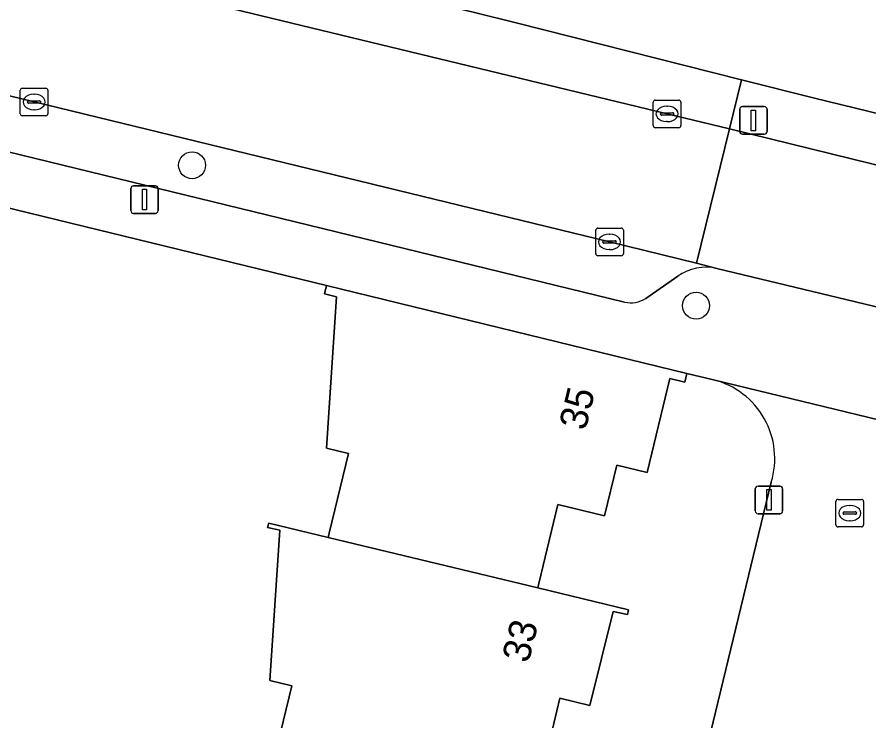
# Model space of a CAD drawing. Extents: x 163266 to 164362, y 381528 to 382286.
# Drawn here: x 163907.07 to 163937.95, y 382191.99 to 382217.52 of the extents above; entities that cross this region are included whole.
import ezdxf

# ---------------------------------------------------------------- set-up
doc = ezdxf.new("R2010")
doc.units = 0
for name, color, linetype in [('IMGEO_Boom', 7, 'Continuous'), ('IMGEO_Erf', 7, 'Continuous'), ('IMGEO_Kolk', 7, 'Continuous'), ('IMGEO_Lichtmast', 7, 'Continuous'), ('IMGEO_Muur', 7, 'Continuous'), ('IMGEO_Pand', 7, 'Continuous'), ('IMGEO_Pand_nummerreeks', 7, 'Continuous'), ('IMGEO_Parkeervlak_open', 7, 'Continuous'), ('IMGEO_Rijbaan_lokaal_open', 7, 'Continuous'), ('IMGEO_Voetpad_open', 7, 'Continuous')]:
    doc.layers.add(name, color=color, linetype=linetype)

msp = doc.modelspace()

# ---------------------------------------------------------------- linework, layer by layer
at = {"layer": 'IMGEO_Boom'}
for centre in [(163913.411, 382212.143), (163931.679, 382207.048)]:
    msp.add_circle(centre, 0.489, dxfattribs=at)
at = {"layer": 'IMGEO_Erf'}
for points in [[(163874.578, 382229.533), (163885.354, 382226.906), (163896.086, 382224.391), (163897.546, 382224.049), (163904.364, 382222.388), (163905.821, 382222.033), (163915.471, 382219.682), (163916.928, 382219.327), (163923.701, 382217.677), (163925.155, 382217.309), (163933.327, 382215.242), (163935.971, 382214.573), (163946.731, 382211.952)], [(163916.321, 382190.367), (163917.025, 382193.254), (163916.228, 382193.448), (163916.587, 382198.902), (163916.15, 382199.008), (163916.188, 382199.164), (163918.345, 382198.644), (163918.383, 382198.799), (163919.084, 382201.69), (163918.288, 382201.883), (163918.644, 382207.371), (163918.206, 382207.474), (163918.282, 382207.785), (163898.197, 382212.679)], [(163932.313, 382204.362), (163931.342, 382204.587), (163931.266, 382204.276), (163930.731, 382204.406), (163929.901, 382200.994), (163928.806, 382201.259), (163928.361, 382199.425), (163926.673, 382199.834), (163925.977, 382196.968), (163925.939, 382196.813), (163929.235, 382196.018), (163929.197, 382195.852), (163928.672, 382195.959), (163927.827, 382192.546), (163926.745, 382192.808), (163926.3, 382190.974)], [(163940.356, 382199.528), (163933.495, 382171.246), (163927.639, 382172.665), (163934.405, 382200.646)]]:
    msp.add_lwpolyline(points, dxfattribs=at)
msp.add_arc((163931.582, 382201.504), 2.95, 343.1002, 75.6563, dxfattribs=at)
at = {"layer": 'IMGEO_Kolk'}
for p, q in [((163907.182, 382214.012), (163907.182, 382214.864)), ((163907.257, 382214.938), (163908.109, 382214.938)), ((163908.183, 382214.864), (163908.183, 382214.012)), ((163907.67, 382214.718), (163907.695, 382214.718)), ((163907.441, 382214.432), (163907.441, 382214.444)), ((163907.879, 382214.395), (163907.481, 382214.395)), ((163907.484, 382214.481), (163907.882, 382214.481)), ((163907.925, 382214.444), (163907.925, 382214.432)), ((163930.126, 382213.579), (163930.126, 382214.431)), ((163930.201, 382214.505), (163931.053, 382214.505)), ((163930.614, 382214.285), (163930.639, 382214.285)), ((163931.127, 382214.431), (163931.127, 382213.579)), ((163908.109, 382213.938), (163907.257, 382213.938)), ((163907.693, 382214.158), (163907.668, 382214.158)), ((163930.385, 382213.999), (163930.385, 382214.011)), ((163930.823, 382213.962), (163930.425, 382213.962)), ((163930.428, 382214.048), (163930.826, 382214.048)), ((163930.869, 382214.011), (163930.869, 382213.999)), ((163930.637, 382213.725), (163930.612, 382213.725)), ((163931.053, 382213.505), (163930.201, 382213.505)), ((163928.042, 382208.937), (163928.042, 382209.789)), ((163928.117, 382209.863), (163928.969, 382209.863)), ((163928.53, 382209.643), (163928.555, 382209.643)), ((163929.043, 382209.789), (163929.043, 382208.937)), ((163928.301, 382209.357), (163928.301, 382209.369)), ((163928.739, 382209.32), (163928.341, 382209.32)), ((163928.344, 382209.406), (163928.742, 382209.406)), ((163928.785, 382209.369), (163928.785, 382209.357)), ((163928.553, 382209.083), (163928.528, 382209.083)), ((163928.969, 382208.863), (163928.117, 382208.863)), ((163936.825, 382200.024), (163937.677, 382200.024)), ((163936.75, 382199.098), (163936.75, 382199.95)), ((163937.238, 382199.804), (163937.263, 382199.804)), ((163937.751, 382199.95), (163937.751, 382199.098)), ((163937.009, 382199.518), (163937.009, 382199.53)), ((163937.447, 382199.481), (163937.049, 382199.481)), ((163937.052, 382199.567), (163937.45, 382199.567)), ((163937.493, 382199.53), (163937.493, 382199.518)), ((163937.261, 382199.244), (163937.236, 382199.244)), ((163937.677, 382199.024), (163936.825, 382199.024))]:
    msp.add_line(p, q, dxfattribs=at)
for points in [[(163907.182, 382214.012), (163907.182, 382214.864)], [(163907.257, 382214.938), (163908.109, 382214.938)], [(163908.183, 382214.864), (163908.183, 382214.012)], [(163930.126, 382213.579), (163930.126, 382214.431)], [(163930.201, 382214.505), (163931.053, 382214.505)], [(163931.127, 382214.431), (163931.127, 382213.579)], [(163908.109, 382213.938), (163907.257, 382213.938)], [(163931.053, 382213.505), (163930.201, 382213.505)], [(163928.042, 382208.937), (163928.042, 382209.789)], [(163928.117, 382209.863), (163928.969, 382209.863)], [(163929.043, 382209.789), (163929.043, 382208.937)], [(163928.969, 382208.863), (163928.117, 382208.863)], [(163936.825, 382200.024), (163937.677, 382200.024)], [(163936.75, 382199.098), (163936.75, 382199.95)], [(163937.751, 382199.95), (163937.751, 382199.098)], [(163937.677, 382199.024), (163936.825, 382199.024)]]:
    msp.add_lwpolyline(points, dxfattribs=at)
for centre, radius, start, end in [((163907.259, 382214.862), 0.0765, 91.552, 178.448), ((163907.259, 382214.862), 0.0765, 91.552, 178.448), ((163908.107, 382214.862), 0.0765, 1.552, 88.448), ((163908.107, 382214.862), 0.0765, 1.552, 88.448), ((163907.481, 382214.441), 0.0403, 85.8775, 175.7526), ((163907.478, 382214.431), 0.0366, 178.938, 274.7102), ((163907.882, 382214.438), 0.043, 264.8664, 352.4533), ((163907.886, 382214.443), 0.0386, 1.7309, 96.639), ((163930.203, 382214.429), 0.0765, 91.552, 178.448), ((163930.203, 382214.429), 0.0765, 91.552, 178.448), ((163931.051, 382214.429), 0.0765, 1.552, 88.448), ((163931.051, 382214.429), 0.0765, 1.552, 88.448), ((163907.259, 382214.014), 0.0765, 181.552, 268.448), ((163907.259, 382214.014), 0.0765, 181.552, 268.448), ((163908.107, 382214.014), 0.0765, 271.552, 358.448), ((163908.107, 382214.014), 0.0765, 271.552, 358.448), ((163930.425, 382214.008), 0.0403, 85.8775, 175.7526), ((163930.422, 382213.998), 0.0366, 178.938, 274.7102), ((163930.826, 382214.005), 0.043, 264.8664, 352.4533), ((163930.83, 382214.01), 0.0386, 1.7309, 96.639), ((163930.203, 382213.581), 0.0765, 181.552, 268.448), ((163930.203, 382213.581), 0.0765, 181.552, 268.448), ((163931.051, 382213.581), 0.0765, 271.552, 358.448), ((163931.051, 382213.581), 0.0765, 271.552, 358.448), ((163928.119, 382209.787), 0.0765, 91.552, 178.448), ((163928.119, 382209.787), 0.0765, 91.552, 178.448), ((163928.967, 382209.787), 0.0765, 1.552, 88.448), ((163928.967, 382209.787), 0.0765, 1.552, 88.448), ((163928.341, 382209.366), 0.0403, 85.8775, 175.7526), ((163928.338, 382209.356), 0.0366, 178.938, 274.7102), ((163928.742, 382209.363), 0.043, 264.8664, 352.4533), ((163928.746, 382209.368), 0.0386, 1.7309, 96.639), ((163928.119, 382208.939), 0.0765, 181.552, 268.448), ((163928.119, 382208.939), 0.0765, 181.552, 268.448), ((163928.967, 382208.939), 0.0765, 271.552, 358.448), ((163928.967, 382208.939), 0.0765, 271.552, 358.448), ((163936.827, 382199.948), 0.0765, 91.552, 178.448), ((163936.827, 382199.948), 0.0765, 91.552, 178.448), ((163937.675, 382199.948), 0.0765, 1.552, 88.448), ((163937.675, 382199.948), 0.0765, 1.552, 88.448), ((163937.049, 382199.527), 0.0403, 85.8775, 175.7526), ((163937.046, 382199.517), 0.0366, 178.938, 274.7102), ((163937.45, 382199.524), 0.043, 264.8664, 352.4533), ((163937.454, 382199.529), 0.0386, 1.7309, 96.639), ((163936.827, 382199.1), 0.0765, 181.552, 268.448), ((163936.827, 382199.1), 0.0765, 181.552, 268.448), ((163937.675, 382199.1), 0.0765, 271.552, 358.448), ((163937.675, 382199.1), 0.0765, 271.552, 358.448)]:
    msp.add_arc(centre, radius, start, end, dxfattribs=at)
for centre, major_axis, ratio, start_param, end_param in [((163907.669, 382214.438), (-0.387, 0.002), 0.722429, 4.712389, 7.853982), ((163907.694, 382214.438), (-0.39, 0.002), 0.717154, 1.570796, 4.712389), ((163930.613, 382214.005), (-0.387, 0.002), 0.722429, 4.712389, 7.853982), ((163930.638, 382214.005), (-0.39, 0.002), 0.717154, 1.570796, 4.712389), ((163928.529, 382209.363), (-0.387, 0.002), 0.722429, 4.712389, 7.853982), ((163928.554, 382209.363), (-0.39, 0.002), 0.717154, 1.570796, 4.712389), ((163937.237, 382199.524), (-0.387, 0.002), 0.722429, 4.712389, 7.853982), ((163937.262, 382199.524), (-0.39, 0.002), 0.717154, 1.570796, 4.712389)]:
    msp.add_ellipse(centre, major_axis=major_axis, ratio=ratio, start_param=start_param, end_param=end_param, dxfattribs=at)
at = {"layer": 'IMGEO_Lichtmast'}
for p, q in [((163933.362, 382214.271), (163934.152, 382214.271)), ((163934.152, 382214.271), (163933.362, 382214.271)), ((163933.262, 382213.371), (163933.262, 382214.171)), ((163933.262, 382214.171), (163933.262, 382213.371)), ((163934.252, 382214.171), (163934.252, 382213.371)), ((163934.252, 382213.371), (163934.252, 382214.171)), ((163934.152, 382213.271), (163933.362, 382213.271)), ((163933.362, 382213.271), (163934.152, 382213.271)), ((163911.189, 382210.497), (163911.189, 382211.297)), ((163911.189, 382211.297), (163911.189, 382210.497)), ((163911.289, 382211.397), (163912.079, 382211.397)), ((163912.079, 382211.397), (163911.289, 382211.397)), ((163912.179, 382211.297), (163912.179, 382210.497)), ((163912.179, 382210.497), (163912.179, 382211.297)), ((163912.079, 382210.397), (163911.289, 382210.397)), ((163911.289, 382210.397), (163912.079, 382210.397)), ((163933.826, 382199.603), (163933.826, 382200.403)), ((163933.826, 382200.403), (163933.826, 382199.603)), ((163933.926, 382200.503), (163934.716, 382200.503)), ((163934.716, 382200.503), (163933.926, 382200.503)), ((163934.816, 382200.403), (163934.816, 382199.603)), ((163934.816, 382199.603), (163934.816, 382200.403)), ((163934.716, 382199.503), (163933.926, 382199.503)), ((163933.926, 382199.503), (163934.716, 382199.503))]:
    msp.add_line(p, q, dxfattribs=at)
for points in [[(163933.682, 382214.146), (163933.832, 382214.146), (163933.832, 382213.396), (163933.682, 382213.396), (163933.682, 382214.146)], [(163911.609, 382211.272), (163911.759, 382211.272), (163911.759, 382210.522), (163911.609, 382210.522), (163911.609, 382211.272)], [(163934.246, 382200.378), (163934.396, 382200.378), (163934.396, 382199.628), (163934.246, 382199.628), (163934.246, 382200.378)]]:
    msp.add_lwpolyline(points, dxfattribs=at)
for centre, start, end in [((163933.362, 382214.171), 90, 180), ((163933.362, 382214.171), 90, 180), ((163934.152, 382214.171), 0, 90), ((163934.152, 382214.171), 360, 90), ((163933.362, 382213.371), 180, 270), ((163933.362, 382213.371), 180, 270), ((163934.152, 382213.371), 270, 0), ((163934.152, 382213.371), 270, 0), ((163911.289, 382211.297), 90, 180), ((163911.289, 382211.297), 90, 180), ((163912.079, 382211.297), 0, 90), ((163912.079, 382211.297), 360, 90), ((163911.289, 382210.497), 180, 270), ((163911.289, 382210.497), 180, 270), ((163912.079, 382210.497), 270, 0), ((163912.079, 382210.497), 270, 0), ((163933.926, 382200.403), 90, 180), ((163933.926, 382200.403), 90, 180), ((163934.716, 382200.403), 0, 90), ((163934.716, 382200.403), 360, 90), ((163933.926, 382199.603), 180, 270), ((163933.926, 382199.603), 180, 270), ((163934.716, 382199.603), 270, 0), ((163934.716, 382199.603), 270, 0)]:
    msp.add_arc(centre, 0.1, start, end, dxfattribs=at)
at = {"layer": 'IMGEO_Muur'}
for points in [[(163925.155, 382217.309), (163933.327, 382215.242)], [(163933.327, 382215.242), (163935.971, 382214.573)], [(163918.282, 382207.785), (163898.197, 382212.679)]]:
    msp.add_lwpolyline(points, dxfattribs=at)
at = {"layer": 'IMGEO_Pand'}
for points in [[(163930.731, 382204.406), (163931.266, 382204.276), (163931.342, 382204.587), (163918.282, 382207.785), (163918.206, 382207.474), (163918.644, 382207.371), (163918.288, 382201.883), (163919.084, 382201.69), (163918.383, 382198.799), (163918.345, 382198.644), (163925.939, 382196.813), (163925.977, 382196.968), (163926.673, 382199.834), (163928.361, 382199.425), (163928.806, 382201.259), (163929.901, 382200.994)], [(163928.672, 382195.959), (163929.197, 382195.852), (163929.235, 382196.018), (163925.939, 382196.813), (163918.345, 382198.644), (163916.188, 382199.164), (163916.15, 382199.008), (163916.587, 382198.902), (163916.228, 382193.448), (163917.025, 382193.254), (163916.321, 382190.367), (163916.283, 382190.212), (163923.878, 382188.362), (163923.916, 382188.517), (163924.612, 382191.383), (163926.3, 382190.974), (163926.745, 382192.808), (163927.827, 382192.546)]]:
    msp.add_lwpolyline(points, close=True, dxfattribs=at)
at = {"layer": 'IMGEO_Parkeervlak_open'}
for points in [[(163932.431, 382208.4), (163931.692, 382208.593), (163928.543, 382209.364), (163907.684, 382214.44), (163888.493, 382219.12), (163886.466, 382219.622), (163885.586, 382219.84)], [(163888.263, 382217.139), (163906.701, 382212.643), (163929.09, 382207.179)], [(163929.853, 382207.315), (163931.021, 382208.117)]]:
    msp.add_lwpolyline(points, dxfattribs=at)
for centre, radius, start, end in [((163932.035, 382206.717), 1.729, 76.7766, 125.9214), ((163929.31, 382208.154), 1, 257.2957, 302.9172)]:
    msp.add_arc(centre, radius, start, end, dxfattribs=at)
at = {"layer": 'IMGEO_Rijbaan_lokaal_open'}
for points in [[(163886.466, 382219.622), (163888.493, 382219.12), (163907.684, 382214.44), (163928.543, 382209.364), (163931.692, 382208.593), (163932.888, 382213.459), (163930.627, 382214.004), (163909.822, 382219.048), (163887.996, 382224.37), (163887.667, 382224.454)], [(163947.637, 382209.835), (163932.888, 382213.459), (163931.692, 382208.593), (163932.431, 382208.4), (163944.694, 382205.452), (163946.457, 382205)]]:
    msp.add_lwpolyline(points, close=True, dxfattribs=at)
for points in [[(163943.13, 382201.736), (163932.313, 382204.362)], [(163934.405, 382200.646), (163927.639, 382172.665), (163933.495, 382171.246), (163940.356, 382199.528)]]:
    msp.add_lwpolyline(points, dxfattribs=at)
msp.add_arc((163931.582, 382201.504), 2.95, 343.1002, 75.6563, dxfattribs=at)
at = {"layer": 'IMGEO_Voetpad_open'}
for points in [[(163870.358, 382228.687), (163887.667, 382224.454), (163887.996, 382224.37), (163909.822, 382219.048), (163930.627, 382214.004), (163932.888, 382213.459), (163933.327, 382215.242), (163925.155, 382217.309), (163923.701, 382217.677), (163916.928, 382219.327), (163915.471, 382219.682), (163905.821, 382222.033), (163904.364, 382222.388), (163897.546, 382224.049), (163896.086, 382224.391), (163885.354, 382226.906), (163874.578, 382229.533)], [(163879.746, 382217.457), (163885.119, 382215.864), (163898.197, 382212.679), (163918.282, 382207.785), (163931.342, 382204.587), (163932.313, 382204.362), (163943.13, 382201.736), (163944.927, 382201.296), (163957.981, 382198.105), (163962.176, 382197.087), (163978.062, 382193.221), (163991.123, 382190.027), (163996.644, 382188.946)], [(163929.09, 382207.179), (163906.701, 382212.643), (163888.263, 382217.139)], [(163946.731, 382211.952), (163935.971, 382214.573), (163933.327, 382215.242), (163932.888, 382213.459), (163947.637, 382209.835)], [(163944.694, 382205.452), (163932.431, 382208.4)], [(163931.021, 382208.117), (163929.853, 382207.315)]]:
    msp.add_lwpolyline(points, dxfattribs=at)
for centre, radius, start, end in [((163932.035, 382206.717), 1.729, 76.7766, 125.9214), ((163929.31, 382208.154), 1, 257.2957, 302.9172)]:
    msp.add_arc(centre, radius, start, end, dxfattribs=at)

# ---------------------------------------------------------------- texts
at = {"layer": 'IMGEO_Pand_nummerreeks'}
for s, rotation, p in [('35', 76.3294, (163927.672, 382202.492)), ('33', 76.0945, (163925.604, 382194.056))]:
    msp.add_text(s, height=1, rotation=rotation, dxfattribs=at).set_placement(p)

doc.saveas('drawing.dxf')
